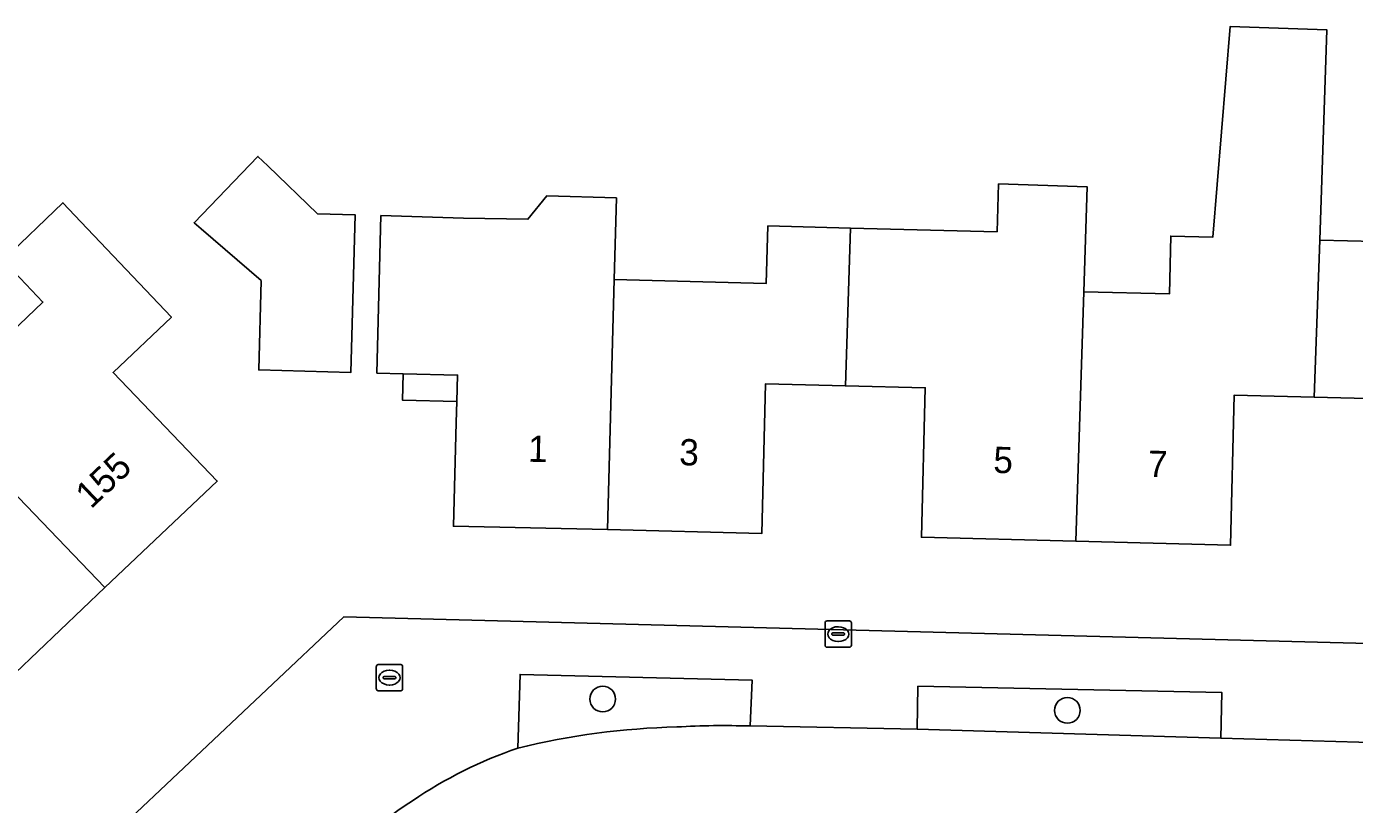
# Model space of a CAD drawing. Extents: x 162082 to 163401, y 388089 to 388636.
# Drawn here: x 162323.5 to 162374, y 388473 to 388502.6 of the extents above; entities that cross this region are included whole.
import ezdxf

# ---------------------------------------------------------------- set-up
doc = ezdxf.new("R2010")
doc.units = 0
for name, color, linetype in [('IMGEO_Boom', 7, 'Continuous'), ('IMGEO_Erf', 7, 'Continuous'), ('IMGEO_Fietspad_gesloten', 7, 'Continuous'), ('IMGEO_Groenvoorziening', 7, 'Continuous'), ('IMGEO_Kolk', 7, 'Continuous'), ('IMGEO_Pand', 7, 'Continuous'), ('IMGEO_Pand_nummerreeks', 7, 'Continuous'), ('IMGEO_Pand_overbouw', 7, 'Continuous'), ('IMGEO_Voetpad_open', 7, 'Continuous')]:
    doc.layers.add(name, color=color, linetype=linetype)

msp = doc.modelspace()

# ---------------------------------------------------------------- linework, layer by layer
at = {"layer": 'IMGEO_Boom'}
for centre in [(162345.413, 388476.993), (162363.097, 388476.562)]:
    msp.add_circle(centre, 0.489, dxfattribs=at)
at = {"layer": 'IMGEO_Erf'}
for points in [[(162375.53, 388488.41), (162372.491, 388488.48), (162369.45, 388488.56), (162369.31, 388482.85), (162363.42, 388483), (162357.54, 388483.15), (162357.69, 388488.84), (162354.65, 388488.91), (162351.61, 388488.99), (162351.47, 388483.3), (162345.6, 388483.44), (162339.73, 388483.57), (162339.84, 388487.521), (162339.862, 388488.32), (162339.89, 388489.32), (162337.817, 388489.374), (162336.82, 388489.4), (162336.945, 388494.399), (162336.97, 388495.39), (162340.12, 388495.3), (162342.567, 388495.253), (162343.283, 388496.142), (162345.932, 388496.067), (162345.85, 388492.955), (162351.64, 388492.81), (162351.7, 388495), (162354.84, 388494.92), (162360.421, 388494.779), (162360.478, 388496.597), (162363.846, 388496.491), (162363.72, 388492.493), (162366.98, 388492.41), (162367.03, 388494.61), (162368.633, 388494.568), (162369.291, 388502.586), (162372.979, 388502.457), (162372.7, 388494.462), (162375.86, 388494.38)], [(162322.87, 388399.024), (162324.944, 388398.956), (162326.67, 388467.741), (162326.772, 388471.823), (162335.557, 388480.119), (162369.201, 388479.245), (162396.51, 388478.538)]]:
    msp.add_lwpolyline(points, dxfattribs=at)
for points in [[(162335.832, 388489.426), (162332.323, 388489.518), (162332.412, 388492.917), (162330.134, 388494.883), (162329.859, 388495.12), (162332.291, 388497.646), (162332.665, 388497.286), (162334.559, 388495.462), (162335.989, 388495.424)], [(162326.78, 388489.42), (162330.74, 388485.29), (162326.47, 388481.24), (162322.2, 388477.18), (162318.25, 388481.32), (162316.04, 388479.21), (162312.594, 388482.833), (162311.93, 388483.53), (162314.21, 388485.7), (162312.825, 388487.149), (162317.002, 388491.142), (162319.896, 388488.082), (162324.11, 388492.1), (162322.59, 388493.7), (162324.87, 388495.88), (162325.557, 388495.156), (162329, 388491.53)]]:
    msp.add_lwpolyline(points, close=True, dxfattribs=at)
at = {"layer": 'IMGEO_Fietspad_gesloten'}
msp.add_lwpolyline([(162529.917, 388471.443), (162485.874, 388472.504), (162448.342, 388473.476), (162416.648, 388474.331), (162416.648, 388474.82), (162409.151, 388475.063), (162409.128, 388474.536), (162400.452, 388474.693), (162389.858, 388475.046), (162386.763, 388475.096), (162375.068, 388475.331), (162368.942, 388475.51), (162357.381, 388475.853), (162351.02, 388475.969)], dxfattribs=at)
for centre, radius, start, end in [((162348.901, 388447.763), 28.176, 91.3477, 103.787), ((162350.045, 388445.487), 30.497, 88.1681, 93.397), ((162347.614, 388459.254), 16.776, 108.8792, 124.2281), ((162348.911, 388456.516), 19.774, 122.8742, 153.8443)]:
    msp.add_arc(centre, radius, start, end, dxfattribs=at)
at = {"layer": 'IMGEO_Groenvoorziening'}
for points in [[(162351.102, 388477.707), (162342.269, 388477.93), (162342.186, 388475.127)], [(162351.02, 388475.969), (162351.102, 388477.707)]]:
    msp.add_lwpolyline(points, dxfattribs=at)
msp.add_lwpolyline([(162368.979, 388477.237), (162357.407, 388477.479), (162357.381, 388475.853), (162368.942, 388475.51)], close=True, dxfattribs=at)
for centre, radius, start, end in [((162348.901, 388447.763), 28.176, 91.3477, 103.787), ((162350.045, 388445.487), 30.497, 88.1681, 93.397)]:
    msp.add_arc(centre, radius, start, end, dxfattribs=at)
at = {"layer": 'IMGEO_Kolk'}
for p, q in [((162353.875, 388479.04), (162353.875, 388479.892)), ((162353.95, 388479.966), (162354.802, 388479.966)), ((162354.363, 388479.746), (162354.388, 388479.746)), ((162354.876, 388479.892), (162354.876, 388479.04)), ((162354.134, 388479.46), (162354.134, 388479.472)), ((162354.572, 388479.423), (162354.174, 388479.423)), ((162354.177, 388479.509), (162354.575, 388479.509)), ((162354.618, 388479.472), (162354.618, 388479.46)), ((162354.802, 388478.966), (162353.95, 388478.966)), ((162354.386, 388479.186), (162354.361, 388479.186)), ((162336.797, 388477.382), (162336.797, 388478.234)), ((162336.872, 388478.308), (162337.724, 388478.308)), ((162337.798, 388478.234), (162337.798, 388477.382)), ((162337.056, 388477.802), (162337.056, 388477.814)), ((162337.494, 388477.765), (162337.096, 388477.765)), ((162337.099, 388477.851), (162337.497, 388477.851)), ((162337.285, 388478.088), (162337.31, 388478.088)), ((162337.54, 388477.814), (162337.54, 388477.802)), ((162337.724, 388477.308), (162336.872, 388477.308)), ((162337.308, 388477.528), (162337.283, 388477.528))]:
    msp.add_line(p, q, dxfattribs=at)
for points in [[(162353.875, 388479.04), (162353.875, 388479.892)], [(162353.95, 388479.966), (162354.802, 388479.966)], [(162354.876, 388479.892), (162354.876, 388479.04)], [(162354.802, 388478.966), (162353.95, 388478.966)], [(162336.797, 388477.382), (162336.797, 388478.234)], [(162336.872, 388478.308), (162337.724, 388478.308)], [(162337.798, 388478.234), (162337.798, 388477.382)], [(162337.724, 388477.308), (162336.872, 388477.308)]]:
    msp.add_lwpolyline(points, dxfattribs=at)
for centre, radius, start, end in [((162353.952, 388479.89), 0.0765, 91.552, 178.448), ((162353.952, 388479.89), 0.0765, 91.552, 178.448), ((162354.8, 388479.89), 0.0765, 1.552, 88.448), ((162354.8, 388479.89), 0.0765, 1.552, 88.448), ((162354.174, 388479.469), 0.0403, 85.8775, 175.7526), ((162354.171, 388479.459), 0.0366, 178.938, 274.7102), ((162354.575, 388479.466), 0.043, 264.8664, 352.4533), ((162354.579, 388479.471), 0.0386, 1.7309, 96.639), ((162353.952, 388479.042), 0.0765, 181.552, 268.448), ((162353.952, 388479.042), 0.0765, 181.552, 268.448), ((162354.8, 388479.042), 0.0765, 271.552, 358.448), ((162354.8, 388479.042), 0.0765, 271.552, 358.448), ((162336.874, 388478.232), 0.0765, 91.552, 178.448), ((162336.874, 388478.232), 0.0765, 91.552, 178.448), ((162337.722, 388478.232), 0.0765, 1.552, 88.448), ((162337.722, 388478.232), 0.0765, 1.552, 88.448), ((162337.096, 388477.811), 0.0403, 85.8775, 175.7526), ((162337.093, 388477.801), 0.0366, 178.938, 274.7102), ((162337.497, 388477.808), 0.043, 264.8664, 352.4533), ((162337.501, 388477.813), 0.0386, 1.7309, 96.639), ((162336.874, 388477.384), 0.0765, 181.552, 268.448), ((162336.874, 388477.384), 0.0765, 181.552, 268.448), ((162337.722, 388477.384), 0.0765, 271.552, 358.448), ((162337.722, 388477.384), 0.0765, 271.552, 358.448)]:
    msp.add_arc(centre, radius, start, end, dxfattribs=at)
for centre, major_axis, ratio, start_param, end_param in [((162354.362, 388479.466), (-0.387, 0.002), 0.722429, 4.712389, 7.853982), ((162354.387, 388479.466), (-0.39, 0.002), 0.717154, 1.570796, 4.712389), ((162337.284, 388477.808), (-0.387, 0.002), 0.722429, 4.712389, 7.853982), ((162337.309, 388477.808), (-0.39, 0.002), 0.717154, 1.570796, 4.712389)]:
    msp.add_ellipse(centre, major_axis=major_axis, ratio=ratio, start_param=start_param, end_param=end_param, dxfattribs=at)
at = {"layer": 'IMGEO_Pand'}
for points in [[(162363.72, 388492.493), (162363.42, 388483), (162369.31, 388482.85), (162369.45, 388488.56), (162372.491, 388488.48), (162372.7, 388494.462), (162372.979, 388502.457), (162369.291, 388502.586), (162368.633, 388494.568), (162367.03, 388494.61), (162366.98, 388492.41)], [(162335.989, 388495.424), (162334.559, 388495.462), (162332.665, 388497.286), (162332.291, 388497.646), (162329.859, 388495.12), (162330.134, 388494.883), (162332.412, 388492.917), (162332.323, 388489.518), (162335.832, 388489.426)], [(162363.72, 388492.493), (162363.846, 388496.491), (162360.478, 388496.597), (162360.421, 388494.779), (162354.84, 388494.92), (162354.65, 388488.91), (162357.69, 388488.84), (162357.54, 388483.15), (162363.42, 388483)], [(162345.6, 388483.44), (162345.85, 388492.955), (162345.932, 388496.067), (162343.283, 388496.142), (162342.567, 388495.253), (162340.12, 388495.3), (162336.97, 388495.39), (162336.945, 388494.399), (162336.82, 388489.4), (162337.817, 388489.374), (162339.89, 388489.32), (162339.862, 388488.32), (162339.84, 388487.521), (162339.73, 388483.57)], [(162326.47, 388481.24), (162330.74, 388485.29), (162326.78, 388489.42), (162329, 388491.53), (162325.557, 388495.156), (162324.87, 388495.88), (162322.59, 388493.7), (162324.11, 388492.1), (162319.896, 388488.082)], [(162345.6, 388483.44), (162351.47, 388483.3), (162351.61, 388488.99), (162354.65, 388488.91), (162354.84, 388494.92), (162351.7, 388495), (162351.64, 388492.81), (162345.85, 388492.955)], [(162372.7, 388494.462), (162372.491, 388488.48), (162375.53, 388488.41), (162375.39, 388482.69), (162381.268, 388482.54), (162381.56, 388492.034), (162375.8, 388492.18), (162375.86, 388494.38)], [(162326.47, 388481.24), (162319.896, 388488.082), (162317.002, 388491.142), (162312.825, 388487.149), (162314.21, 388485.7), (162311.93, 388483.53), (162312.594, 388482.833), (162316.04, 388479.21), (162318.25, 388481.32), (162322.2, 388477.18)]]:
    msp.add_lwpolyline(points, close=True, dxfattribs=at)
at = {"layer": 'IMGEO_Pand_overbouw'}
msp.add_lwpolyline([(162339.862, 388488.32), (162339.89, 388489.32), (162337.817, 388489.374), (162337.789, 388488.374)], close=True, dxfattribs=at)
at = {"layer": 'IMGEO_Voetpad_open'}
for points in [[(162417.147, 388477.667), (162417.157, 388478.082), (162417.228, 388480.994), (162415.103, 388481.036), (162410.079, 388481.141), (162410.008, 388478.167), (162400.65, 388478.41), (162396.51, 388478.538), (162369.201, 388479.245), (162335.557, 388480.119), (162326.772, 388471.823), (162326.67, 388467.741), (162328.425, 388466.717), (162331.162, 388465.233)], [(162342.186, 388475.127), (162342.269, 388477.93), (162351.102, 388477.707), (162351.02, 388475.969), (162357.381, 388475.853), (162357.407, 388477.479), (162368.979, 388477.237), (162368.942, 388475.51), (162375.068, 388475.331), (162375.087, 388477.102), (162386.752, 388476.785), (162386.763, 388475.096), (162389.858, 388475.046), (162389.902, 388476.672), (162400.467, 388476.399), (162400.452, 388474.693), (162409.128, 388474.536), (162409.151, 388475.063), (162416.648, 388474.82), (162416.648, 388474.331), (162448.342, 388473.476), (162485.874, 388472.504), (162529.917, 388471.443)]]:
    msp.add_lwpolyline(points, dxfattribs=at)
for centre, radius, start, end in [((162347.614, 388459.254), 16.776, 108.8792, 124.2281), ((162348.911, 388456.516), 19.774, 122.8742, 153.8443)]:
    msp.add_arc(centre, radius, start, end, dxfattribs=at)

# ---------------------------------------------------------------- texts
at = {"layer": 'IMGEO_Pand_nummerreeks'}
for s, rotation, p in [('1', 358.6825, (162342.562, 388486.026)), ('3', 358.6825, (162348.318, 388485.894)), ('155', 43.5206, (162325.936, 388484.203)), ('5', 358.5399, (162360.271, 388485.601)), ('7', 358.5399, (162366.156, 388485.451))]:
    msp.add_text(s, height=1, rotation=rotation, dxfattribs=at).set_placement(p)

doc.saveas('drawing.dxf')
